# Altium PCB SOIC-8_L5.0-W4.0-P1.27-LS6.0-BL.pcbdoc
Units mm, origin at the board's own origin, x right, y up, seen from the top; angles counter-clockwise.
Board outline 17.7 x 20.06 mm, 2 copper layers (Top Layer, Bottom Layer), stack 0.07 mm thick; 1 components, 0 nets, 8 pads, 0 vias.
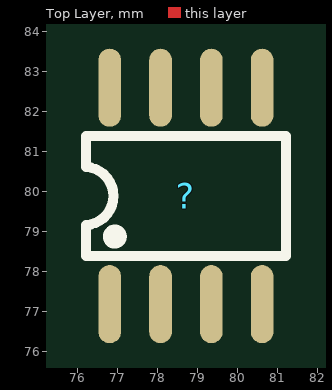
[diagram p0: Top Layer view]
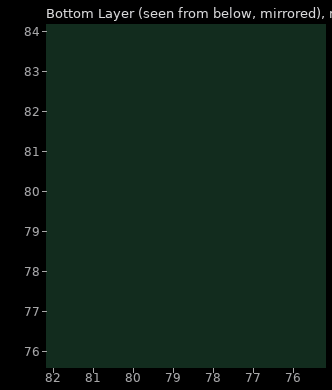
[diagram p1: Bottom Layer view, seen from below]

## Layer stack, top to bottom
Top Solder Mask Layer: solder mask 0.01, Dk 3.3
Top Layer: signal copper 0.035
Bottom Layer: signal copper 0.035
Bottom Solder Mask Layer: solder mask 0.01, Dk 3.3

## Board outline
87.55,69.85 69.85,69.85 69.85,89.91 87.55,89.91

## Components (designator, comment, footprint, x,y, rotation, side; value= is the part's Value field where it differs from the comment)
? "SOIC-8_L5.0-W4.0-P1.27-LS6.0-BL" SOIC-8_L5.0-W4.0-P1.27-LS6.0-BL 78.7,79.88 r0 top

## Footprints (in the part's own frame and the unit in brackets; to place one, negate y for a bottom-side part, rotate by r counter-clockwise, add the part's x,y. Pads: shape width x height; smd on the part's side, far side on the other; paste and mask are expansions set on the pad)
SOIC-8_L5.0-W4.0-P1.27-LS6.0-BL [mil]
  oval 22.38x76.78 smd paste+0 mask+2: 1(-75,-106.5) 2(-25,-106.5) 3(25,-106.5) 4(75,-106.5) 5(75,106.5) 6(25,106.5) 7(-25,106.5) 8(-75,106.5)
  silkscreen extent -98,-59 98,59

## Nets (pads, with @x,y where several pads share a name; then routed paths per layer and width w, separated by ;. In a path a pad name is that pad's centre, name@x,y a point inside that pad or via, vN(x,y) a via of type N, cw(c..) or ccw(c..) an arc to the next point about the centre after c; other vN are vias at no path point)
pads on no net: ?.1 ?.2 ?.3 ?.4 ?.5 ?.6 ?.7 ?.8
